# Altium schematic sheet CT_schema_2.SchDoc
size 287 x 169 mm
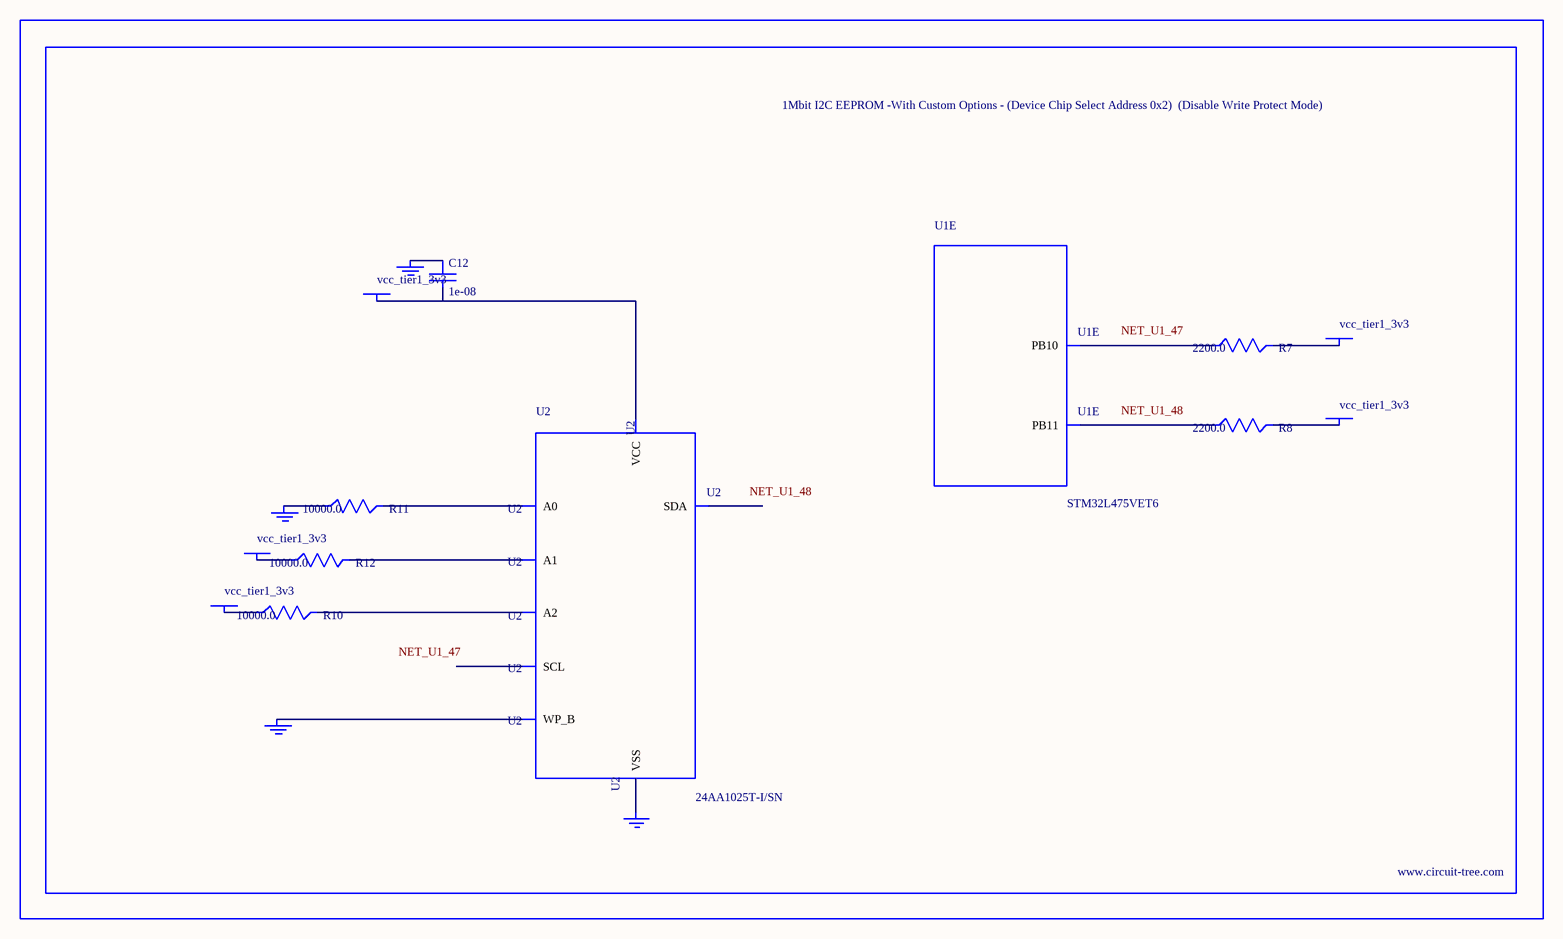
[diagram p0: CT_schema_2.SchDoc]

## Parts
BORDER1  (no value)
C12  1e-08  [C0402]
GND_INSTANCE_1_0  (no value)
GND_INSTANCE_1_1  (no value)
GND_INSTANCE_1_2  (no value)
GND_INSTANCE_1_3  (no value)
POWER_INSTANCE_1_0  vcc_tier1_3v3
POWER_INSTANCE_1_1  vcc_tier1_3v3
POWER_INSTANCE_1_2  vcc_tier1_3v3
POWER_INSTANCE_1_3  vcc_tier1_3v3
POWER_INSTANCE_1_4  vcc_tier1_3v3
R7  2200.0  [R0603]
R8  2200.0  [R0603]
R10  10000.0  [R0603]
R11  10000.0  [R0603]
R12  10000.0  [R0603]
U1  STM32L475VET6  [LQFP100]  (part E of 9)
U2  24AA1025T-I/SN  [SOIC-8]

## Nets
NetC12_1: C12.1 GND_INSTANCE_1_2.0(GND)
NetC12_2: C12.2 POWER_INSTANCE_1_2.0(PWR) U2.8(VCC)
NetGND_INSTANCE_1_0_0: GND_INSTANCE_1_0.0(GND) R11.1
NetGND_INSTANCE_1_1_0: GND_INSTANCE_1_1.0(GND) U2.7(WP_B)
NetGND_INSTANCE_1_3_0: GND_INSTANCE_1_3.0(GND) U2.4(VSS)
NetPOWER_INSTANCE_1_0_0: POWER_INSTANCE_1_0.0(PWR) R12.1
NetPOWER_INSTANCE_1_1_0: POWER_INSTANCE_1_1.0(PWR) R10.1
NetPOWER_INSTANCE_1_3_0: POWER_INSTANCE_1_3.0(PWR) R7.2
NetPOWER_INSTANCE_1_4_0: POWER_INSTANCE_1_4.0(PWR) R8.2
NetR7_1: R7.1 U1.47(PB10)
NetR8_1: R8.1 U1.48(PB11)
NetR10_2: R10.2 U2.3(A2)
NetR11_2: R11.2 U2.1(A0)
NetR12_2: R12.2 U2.2(A1)

Not connected (* = marked no-connect by the designer): U2 5(SDA) 6(SCL)

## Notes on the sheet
- Labels drawn without touching a wire or pin: NET_U1_47, NET_U1_48

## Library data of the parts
BORDER1 = BORDER_PAGE1
C12 = C0402C103K3RAC
GND_INSTANCE_1_0-GND_INSTANCE_1_3 = GND
POWER_INSTANCE_1_0-POWER_INSTANCE_1_4 = PWR
R7 R8 = RC0603JR-072K2L
R10-R12 = RC0603JR-0710KL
